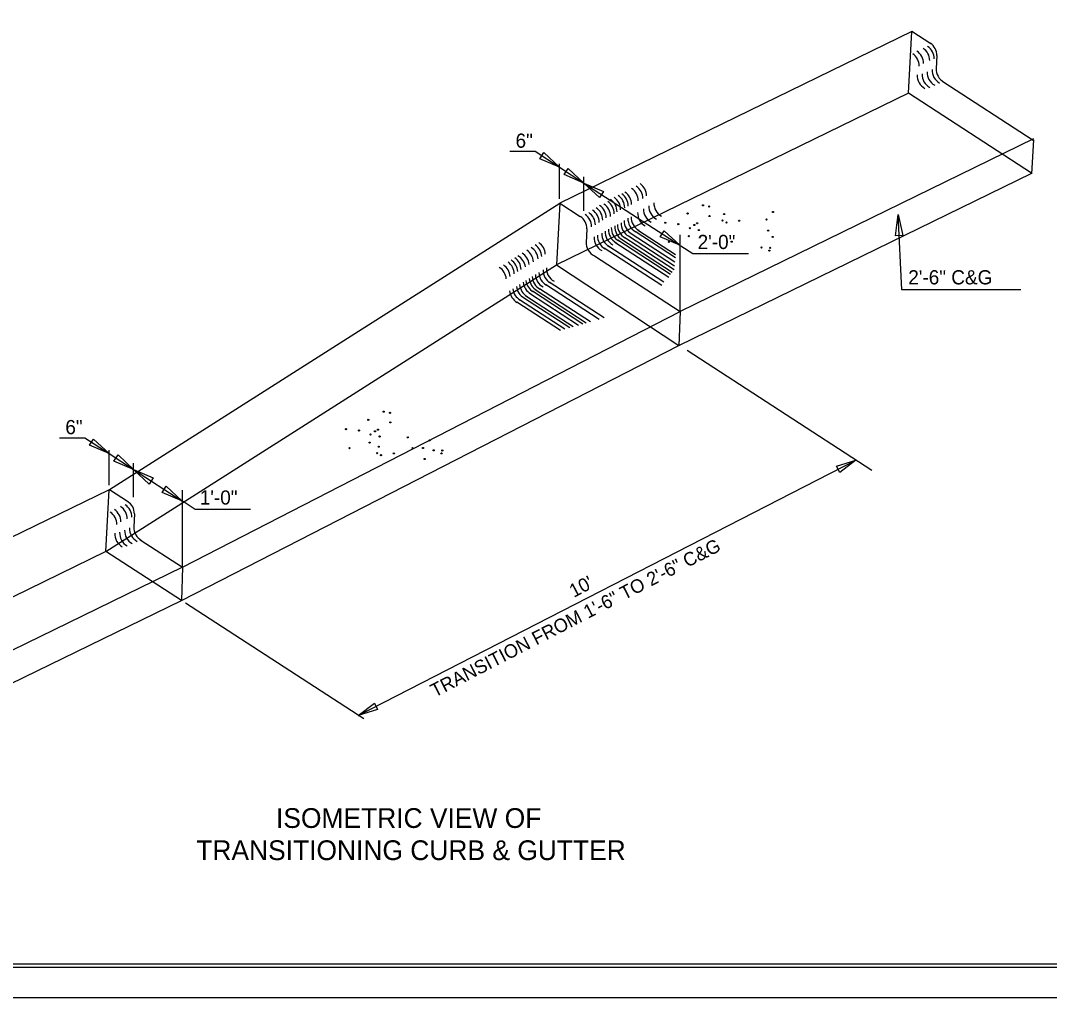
# Model space of a CAD drawing. Extents: x 1252282 to 1252460, y 733735 to 733845.
# Drawn here: x 1252344.6 to 1252421, y 733734.5 to 733807 of the extents above; entities that cross this region are included whole.
import ezdxf

# ---------------------------------------------------------------- set-up
doc = ezdxf.new("R2010")
doc.units = 0
for name, color, linetype in [('Default', 7, 'Continuous'), ('Old_Level_2', 7, 'Continuous'), ('Sheet Cutting Line CELL', 7, 'Continuous'), ('Sheet Plot Border Inside CELL', 7, 'Continuous'), ('Sheet Plot Border Outside CELL', 7, 'Continuous'), ('Sheet Typical CELL', 7, 'Continuous')]:
    doc.layers.add(name, color=color, linetype=linetype)

msp = doc.modelspace()

# ---------------------------------------------------------------- linework, layer by layer
at = {"layer": 'Default'}
for p, q in [((1252410.792, 733806.243), (1252384.634, 733793.486)), ((1252410.55, 733801.663), (1252410.792, 733806.243)), ((1252410.809, 733806.251), (1252412.218, 733805.338)), ((1252412.663, 733804.461), (1252412.615, 733803.482)), ((1252413.1, 733802.529), (1252419.824, 733798.164)), ((1252410.55, 733801.663), (1252384.388, 733788.904)), ((1252419.705, 733795.717), (1252410.55, 733801.663)), ((1252419.845, 733798.259), (1252393.598, 733785.434)), ((1252419.842, 733798.195), (1252419.705, 733795.651)), ((1252384.616, 733793.817), (1252384.616, 733796.405)), ((1252384.616, 733796.158), (1252386.429, 733794.981)), ((1252393.475, 733782.921), (1252419.709, 733795.714)), ((1252386.428, 733794.981), (1252393.549, 733790.355)), ((1252386.429, 733792.913), (1252386.429, 733795.444)), ((1252351.176, 733772.213), (1252384.634, 733793.486)), ((1252384.634, 733793.486), (1252384.388, 733788.904)), ((1252384.634, 733793.486), (1252386.16, 733792.494)), ((1252386.643, 733791.589), (1252386.59, 733790.539)), ((1252389.737, 733791.056), (1252393.168, 733788.829)), ((1252389.945, 733791.232), (1252393.186, 733789.129)), ((1252390.231, 733791.4), (1252393.23, 733789.455)), ((1252390.408, 733791.515), (1252393.234, 733789.68)), ((1252393.598, 733785.434), (1252393.598, 733791.14)), ((1252388.207, 733790.35), (1252392.37, 733787.647)), ((1252388.741, 733790.584), (1252392.74, 733787.987)), ((1252388.952, 733790.761), (1252392.868, 733788.216)), ((1252389.142, 733790.858), (1252392.987, 733788.357)), ((1252389.486, 733790.933), (1252393.15, 733788.551)), ((1252393.646, 733790.325), (1252394.537, 733789.747)), ((1252387.218, 733789.575), (1252393.598, 733785.434)), ((1252387.934, 733790.179), (1252392.233, 733787.387)), ((1252350.917, 733767.625), (1252384.388, 733788.904)), ((1252384.388, 733788.904), (1252393.475, 733782.921)), ((1252383.577, 733787.471), (1252387.573, 733784.877)), ((1252383.851, 733787.643), (1252387.946, 733784.983)), ((1252381.945, 733786.491), (1252385.397, 733784.253)), ((1252382.121, 733786.606), (1252385.64, 733784.322)), ((1252382.398, 733786.793), (1252386.03, 733784.434)), ((1252382.609, 733786.97), (1252386.364, 733784.53)), ((1252382.799, 733787.067), (1252386.598, 733784.597)), ((1252383.143, 733787.142), (1252386.918, 733784.689)), ((1252381.451, 733786.147), (1252384.685, 733784.049)), ((1252381.658, 733786.324), (1252385.017, 733784.144)), ((1252356.6, 733766.457), (1252393.598, 733785.434)), ((1252393.598, 733785.434), (1252393.475, 733782.921)), ((1252356.518, 733763.987), (1252393.475, 733782.921)), ((1252407.836, 733773.622), (1252394.111, 733782.536)), ((1252351.158, 733772.544), (1252351.158, 733775.133)), ((1252351.158, 733774.886), (1252352.97, 733773.708)), ((1252352.97, 733771.64), (1252352.97, 733774.171)), ((1252369.662, 733755.449), (1252406.646, 733774.397)), ((1252352.97, 733773.704), (1252356.551, 733771.379)), ((1252351.159, 733772.205), (1252325, 733759.448)), ((1252350.917, 733767.625), (1252351.159, 733772.205)), ((1252351.176, 733772.213), (1252352.584, 733771.3)), ((1252356.599, 733766.458), (1252356.599, 733772.163)), ((1252356.648, 733771.348), (1252357.539, 733770.77)), ((1252353.03, 733770.423), (1252352.981, 733769.444)), ((1252353.466, 733768.492), (1252356.6, 733766.457)), ((1252350.917, 733767.625), (1252324.683, 733754.831)), ((1252356.518, 733763.987), (1252350.917, 733767.625)), ((1252356.6, 733766.457), (1252330.448, 733753.679)), ((1252356.6, 733766.457), (1252356.518, 733763.987)), ((1252330.284, 733751.193), (1252356.518, 733763.987)), ((1252370.08, 733755.178), (1252356.822, 733763.79))]:
    msp.add_line(p, q, dxfattribs=at)
for points in [[(1252380.921, 733797.335), (1252382.804, 733797.335), (1252384.616, 733796.158)], [(1252418.908, 733787.043), (1252410.054, 733787.043), (1252409.789, 733792.639)], [(1252394.537, 733789.747), (1252398.664, 733789.747)], [(1252347.463, 733776.063), (1252349.346, 733776.063), (1252351.158, 733774.886)], [(1252357.539, 733770.77), (1252361.666, 733770.77)]]:
    msp.add_lwpolyline(points, dxfattribs=at)
for points in [[(1252386.428, 733794.981), (1252387.888, 733794.359), (1252387.588, 733793.896)], [(1252393.549, 733790.355), (1252392.09, 733790.977), (1252392.39, 733791.44)], [(1252406.646, 733774.397), (1252405.44, 733773.488), (1252405.205, 733773.957)], [(1252352.97, 733773.704), (1252354.43, 733773.082), (1252354.13, 733772.619)], [(1252356.551, 733771.379), (1252355.091, 733772), (1252355.391, 733772.463)], [(1252369.662, 733755.449), (1252370.869, 733756.358), (1252371.103, 733755.889)]]:
    msp.add_lwpolyline(points, close=True, dxfattribs=at)
for centre in [(1252395.285, 733793.325), (1252395.748, 733793.24), (1252394.139, 733792.722), (1252395.771, 733792.531), (1252396.853, 733792.676), (1252400.482, 733792.83), (1252392.481, 733792.03), (1252393.449, 733791.93), (1252394.636, 733791.867), (1252394.854, 733791.992), (1252396.732, 733792.196), (1252397.025, 733792.045), (1252397.972, 733792.181), (1252400, 733792.268), (1252394.237, 733791.034), (1252394.298, 733791.633), (1252394.978, 733791.488), (1252400.123, 733791.448), (1252400.463, 733790.979), (1252392.738, 733790.615), (1252397.418, 733790.622), (1252399.625, 733790.19), (1252400.216, 733789.963), (1252400.272, 733790.171), (1252371.557, 733777.996), (1252370.411, 733777.394), (1252372.02, 733777.912), (1252372.043, 733777.203), (1252368.754, 733776.701), (1252369.722, 733776.601), (1252370.908, 733776.539), (1252371.126, 733776.663), (1252370.509, 733775.705), (1252370.571, 733776.305), (1252371.25, 733776.159), (1252373.341, 733776.095), (1252374.956, 733775.87), (1252369.01, 733775.287), (1252371.065, 733774.919), (1252371.186, 733775.399), (1252372.305, 733774.903), (1252373.69, 733775.294), (1252374.475, 733775.308), (1252375.264, 733775.131), (1252375.855, 733774.904), (1252375.911, 733775.112), (1252371.358, 733774.768), (1252374.598, 733774.488)]:
    msp.add_circle(centre, 0.0425, dxfattribs=at)
for centre, start, end in [((1252410.573, 733803.862), 359.51736, 56.42547), ((1252411.036, 733804.079), 359.51736, 56.42547), ((1252411.374, 733804.212), 359.51736, 56.42547), ((1252411.57, 733804.454), 359.51736, 56.42547), ((1252410.261, 733803.668), 359.51736, 56.42547), ((1252413.026, 733803.196), 177.44979, 241.21224), ((1252413.396, 733803.358), 177.44979, 241.21224), ((1252413.709, 733803.439), 177.44979, 241.21224), ((1252412.291, 733802.964), 177.44979, 241.21224), ((1252412.656, 733803.035), 177.44979, 241.21224), ((1252389.998, 733794.027), 359.51736, 56.42547), ((1252388.37, 733793.148), 359.51736, 56.42547), ((1252388.638, 733793.273), 359.51736, 56.42547), ((1252388.876, 733793.399), 359.51736, 56.42547), ((1252389.376, 733793.668), 359.51736, 56.42547), ((1252389.716, 733793.831), 359.51736, 56.42547), ((1252386.998, 733792.404), 359.51736, 56.42547), ((1252387.319, 733792.502), 359.51736, 56.42547), ((1252387.599, 733792.711), 359.51736, 56.42547), ((1252387.8, 733792.862), 359.51736, 56.42547), ((1252388.07, 733793.01), 359.51736, 56.42547), ((1252392.355, 733793.246), 177.44979, 241.21224), ((1252392.728, 733793.467), 177.44979, 241.21224), ((1252385.915, 733791.744), 359.51736, 56.42547), ((1252386.192, 733791.876), 359.51736, 56.42547), ((1252386.471, 733792.061), 359.51736, 56.42547), ((1252386.735, 733792.24), 359.51736, 56.42547), ((1252391.515, 733792.747), 177.44979, 241.21224), ((1252391.951, 733793.026), 177.44979, 241.21224), ((1252385.556, 733791.584), 359.51736, 56.42547), ((1252389.81, 733791.746), 177.44979, 241.21224), ((1252390.024, 733791.858), 177.44979, 241.21224), ((1252390.285, 733791.983), 177.44979, 241.21224), ((1252390.517, 733792.156), 177.44979, 241.21224), ((1252390.796, 733792.319), 177.44979, 241.21224), ((1252391.033, 733792.429), 177.44979, 241.21224), ((1252388.541, 733791.05), 177.44979, 241.21224), ((1252388.849, 733791.203), 177.44979, 241.21224), ((1252389.096, 733791.352), 177.44979, 241.21224), ((1252389.351, 733791.508), 177.44979, 241.21224), ((1252389.558, 733791.636), 177.44979, 241.21224), ((1252382.211, 733789.465), 3.44739, 57.06711), ((1252382.475, 733789.644), 2.81233, 56.42547), ((1252387.686, 733790.561), 177.44979, 244.61403), ((1252388.28, 733790.925), 177.44979, 241.21224), ((1252380.996, 733788.63), 6.77949, 60.53272), ((1252381.277, 733788.839), 5.22971, 58.92983), ((1252381.586, 733789.084), 2.7021, 56.42547), ((1252381.932, 733789.279), 3.89374, 57.53361), ((1252379.574, 733787.775), 4.61403, 58.52381), ((1252379.853, 733787.984), 2.95335, 56.42547), ((1252380.159, 733788.23), 0.23275, 54.28443), ((1252380.428, 733788.355), 2.5582, 56.42547), ((1252380.675, 733788.531), 1.54431, 55.43838), ((1252384.74, 733788.644), 177.44979, 241.21224), ((1252383.681, 733788.067), 182.05696, 241.21224), ((1252383.923, 733788.217), 181.92789, 241.21224), ((1252384.184, 733788.342), 179.90337, 241.21224), ((1252384.493, 733788.495), 177.44979, 241.21224), ((1252382.509, 733787.41), 185.98874, 241.21224), ((1252382.746, 733787.521), 184.09669, 241.21224), ((1252383.008, 733787.717), 185.72201, 241.21224), ((1252383.215, 733787.845), 185.62141, 241.21224), ((1252383.467, 733787.955), 183.19724, 241.21224), ((1252381.999, 733787.075), 185.24585, 241.21224), ((1252382.231, 733787.248), 186.58538, 241.21224), ((1252351.936, 733770.416), 359.51736, 56.42547), ((1252350.627, 733769.63), 359.51736, 56.42547), ((1252350.939, 733769.824), 359.51736, 56.42547), ((1252351.402, 733770.041), 359.51736, 56.42547), ((1252351.741, 733770.174), 359.51736, 56.42547), ((1252352.657, 733768.926), 177.44979, 241.21224), ((1252353.022, 733768.997), 177.44979, 241.21224), ((1252353.392, 733769.158), 177.44979, 241.21224), ((1252353.762, 733769.32), 177.44979, 241.21224), ((1252354.075, 733769.401), 177.44979, 241.21224)]:
    msp.add_arc(centre, 1.092, start, end, dxfattribs=at)
at = {"layer": 'Old_Level_2'}
for points in [[(1252384.616, 733796.158), (1252383.157, 733796.78), (1252383.457, 733797.243)], [(1252386.429, 733794.981), (1252384.969, 733795.602), (1252385.269, 733796.065)], [(1252409.789, 733792.639), (1252410.138, 733791.091), (1252409.587, 733791.065)], [(1252351.158, 733774.886), (1252349.699, 733775.507), (1252349.998, 733775.97)], [(1252352.97, 733773.708), (1252351.511, 733774.33), (1252351.811, 733774.793)]]:
    msp.add_lwpolyline(points, close=True, dxfattribs=at)
at = {"layer": 'Sheet Cutting Line CELL'}
msp.add_line((1252282.183, 733734.502), (1252450.583, 733734.502), dxfattribs=at)
at = {"layer": 'Sheet Plot Border Inside CELL'}
msp.add_lwpolyline([(1252450.133, 733842.257), (1252283.483, 733842.257), (1252283.483, 733736.747), (1252450.133, 733736.747)], close=True, dxfattribs=at)
at = {"layer": 'Sheet Plot Border Outside CELL'}
msp.add_lwpolyline([(1252450.583, 733844.502), (1252282.183, 733844.502), (1252282.183, 733734.502), (1252450.583, 733734.502)], close=True, dxfattribs=at)
at = {"layer": 'Sheet Typical CELL'}
msp.add_lwpolyline([(1252448.883, 733842.002), (1252298.883, 733842.002), (1252298.883, 733737.002), (1252448.883, 733737.002)], close=True, dxfattribs=at)

# ---------------------------------------------------------------- texts
at = {"layer": 'Default'}
for s, height, p in [('6"', 1.0539, (1252381.353, 733797.6)), ('2\'-0"', 1.0539, (1252394.881, 733790.078)), ('2\'-6" C&G', 1.0539, (1252410.535, 733787.453)), ('6"', 1.0539, (1252347.895, 733776.328)), ('1\'-0"', 1.0539, (1252357.883, 733771.101)), ('ISOMETRIC VIEW OF ', 1.46616, (1252363.553, 733747.089)), ('TRANSITIONING CURB & GUTTER', 1.46616, (1252357.626, 733744.701))]:
    msp.add_text(s, height=height, dxfattribs=at).set_placement(p)
for s, height, rotation, p in [('TRANSITION FROM 1\'-6" TO 2\'-6" C&G', 1.00117, 27.1966, (1252375.353, 733756.761)), ("10'", 1.0012, 27.99715, (1252385.681, 733764.164))]:
    msp.add_text(s, height=height, rotation=rotation, dxfattribs=at).set_placement(p)

doc.saveas('drawing.dxf')
